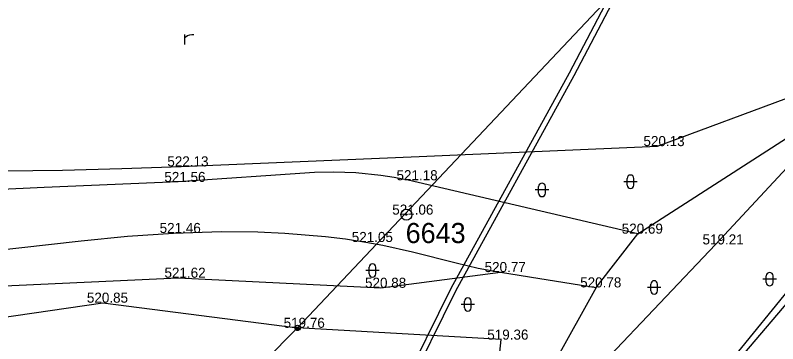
# Model space of a CAD drawing. Extents: x -669393 to -668650, y -1126925 to -1126294.
# Drawn here: x -668824.1 to -668767.3, y -1126837.8 to -1126813.3 of the extents above; entities that cross this region are included whole.
import ezdxf

# ---------------------------------------------------------------- set-up
doc = ezdxf.new("R2010")
doc.units = 0
for name, color, linetype in [('G_Bod_tecka', 7, 'Continuous'), ('G_Bod_vyska', 7, 'Continuous'), ('G_Bodove_pole', 7, 'Continuous'), ('G_Breh_Teren', 7, 'Continuous'), ('G_Plochy_zpevnene', 7, 'Continuous'), ('G_Site-Sloupy', 7, 'Continuous'), ('G_Z_ELsilove_nadz_kotovane', 7, 'Continuous'), ('G_Z_ELsilove_podz_kotovane', 7, 'Continuous'), ('G_Zelen-Znacky', 7, 'Continuous')]:
    doc.layers.add(name, color=color, linetype=linetype)

msp = doc.modelspace()

# ---------------------------------------------------------------- linework, layer by layer
at = {"layer": 'G_Bod_tecka'}
for p, q in [((-668776.23, -1126823.06), (-668776.23, -1126823.06)), ((-668811.72, -1126824.57), (-668811.72, -1126824.57)), ((-668811.94, -1126825.73), (-668811.94, -1126825.73)), ((-668794.8, -1126825.6), (-668794.8, -1126825.6)), ((-668794.93, -1126828.16), (-668794.93, -1126828.16)), ((-668812.28, -1126829.53), (-668812.28, -1126829.53)), ((-668777.69, -1126829.58), (-668777.69, -1126829.58)), ((-668797.96, -1126830.2), (-668797.96, -1126830.2)), ((-668771.91, -1126830.38), (-668771.91, -1126830.38)), ((-668787.92, -1126832.44), (-668787.92, -1126832.44)), ((-668811.93, -1126832.86), (-668811.93, -1126832.86)), ((-668796.83, -1126833.61), (-668796.83, -1126833.61)), ((-668780.8, -1126833.58), (-668780.8, -1126833.58)), ((-668817.55, -1126834.72), (-668817.55, -1126834.72)), ((-668803.04, -1126836.59), (-668803.04, -1126836.59)), ((-668787.87, -1126837.47), (-668787.87, -1126837.47))]:
    msp.add_line(p, q, dxfattribs=at)
at = {"layer": 'G_Bodove_pole'}
for radius in [0.412, 0.05]:
    msp.add_circle((-668794.93, -1126828.16), radius, dxfattribs=at)
at = {"layer": 'G_Breh_Teren'}
for p, q in [((-668757.59, -1126814.98), (-668771.91, -1126830.38)), ((-668772.4, -1126841.08), (-668751.76, -1126815.63)), ((-668776.23, -1126823.06), (-668765.35, -1126819.01)), ((-668777.69, -1126829.58), (-668765.86, -1126821.98)), ((-668771.91, -1126830.38), (-668789.08, -1126848.46)), ((-668796.83, -1126833.61), (-668787.92, -1126832.44)), ((-668827.59, -1126833.6), (-668811.93, -1126832.86)), ((-668811.93, -1126832.86), (-668796.83, -1126833.61)), ((-668780.8, -1126833.58), (-668789.08, -1126848.46)), ((-668830.9, -1126836.66), (-668817.55, -1126834.72)), ((-668817.55, -1126834.72), (-668803.04, -1126836.59)), ((-668787.87, -1126837.47), (-668803.04, -1126836.59)), ((-668789.08, -1126848.46), (-668787.87, -1126837.47))]:
    msp.add_line(p, q, dxfattribs=at)
msp.add_lwpolyline([(-668861.76, -1126825.07), (-668854.42, -1126825.02), (-668847.08, -1126824.98), (-668829.4, -1126824.94), (-668820.56, -1126824.84), (-668816.14, -1126824.73), (-668811.72, -1126824.57), (-668793.98, -1126823.82), (-668776.23, -1126823.06)], dxfattribs=at)
at = {"layer": 'G_Plochy_zpevnene'}
for p, q in [((-668785.44, -1126856.91), (-668751.27, -1126816.73)), ((-668777.69, -1126829.58), (-668794.8, -1126825.6)), ((-668780.8, -1126833.58), (-668777.69, -1126829.58))]:
    msp.add_line(p, q, dxfattribs=at)
for points in [[(-668794.8, -1126825.6), (-668795.84, -1126825.39), (-668796.83, -1126825.24), (-668798.69, -1126825.06), (-668800.34, -1126825.01), (-668801.78, -1126825.02), (-668811.94, -1126825.73), (-668821.93, -1126826.15), (-668831.92, -1126826.62), (-668839.86, -1126827.06), (-668847.81, -1126827.52), (-668851.35, -1126827.68), (-668854.02, -1126827.75), (-668858.01, -1126827.77), (-668862, -1126827.68), (-668863.7, -1126827.58), (-668865.18, -1126827.44), (-668867.77, -1126827.06), (-668869.7, -1126826.68), (-668871.12, -1126826.34), (-668873.25, -1126825.74), (-668875.33, -1126825.04), (-668886.78, -1126820.88), (-668897.18, -1126817.23)], [(-668826.04, -1126830.87), (-668819.16, -1126830.1), (-668815.72, -1126829.77), (-668812.28, -1126829.53), (-668808.7, -1126829.42), (-668806.01, -1126829.44), (-668803.99, -1126829.53), (-668800.97, -1126829.78), (-668799.46, -1126829.97), (-668797.96, -1126830.2), (-668796.69, -1126830.43), (-668794.49, -1126830.94), (-668791.22, -1126831.76), (-668789.58, -1126832.14), (-668787.92, -1126832.44), (-668784.36, -1126833.01), (-668780.8, -1126833.58)]]:
    msp.add_lwpolyline(points, dxfattribs=at)
at = {"layer": 'G_Site-Sloupy'}
msp.add_circle((-668803.04, -1126836.59), 0.2, dxfattribs=at)
for radius in [0.18, 0.16, 0.14, 0.12, 0.1, 0.08, 0.06, 0.04, 0.02]:
    msp.add_arc((-668803.04, -1126836.59), radius, 180, 0, dxfattribs=at)
at = {"layer": 'G_Z_ELsilove_nadz_kotovane'}
msp.add_lwpolyline([(-668760.642, -1126791.685), (-668778.872, -1126810.991), (-668779.891, -1126812.071), (-668803.039, -1126836.585), (-668840.228, -1126874.108)], dxfattribs=at)
at = {"layer": 'G_Z_ELsilove_podz_kotovane'}
for points in [[(-668689.689, -1126700.721), (-668717.926, -1126737.102), (-668731.142, -1126751.223), (-668740.945, -1126761.054), (-668764.235, -1126785.249), (-668764.468, -1126785.599), (-668771.608, -1126796.321), (-668779.891, -1126812.071), (-668782.816, -1126817.632), (-668791.63, -1126833.665), (-668795.332, -1126841.155), (-668801.598, -1126850.336), (-668806.75, -1126857.548), (-668807.082, -1126858.921), (-668805.909, -1126860.176), (-668789.068, -1126872.587), (-668784.608, -1126876.148)], [(-668689.548, -1126701.19), (-668717.622, -1126737.362), (-668730.854, -1126751.501), (-668740.659, -1126761.334), (-668763.921, -1126785.501), (-668764.234, -1126785.971), (-668771.264, -1126796.525), (-668778.872, -1126810.991), (-668782.464, -1126817.822), (-668791.276, -1126833.851), (-668794.986, -1126841.357), (-668801.27, -1126850.566), (-668806.38, -1126857.718), (-668806.642, -1126858.805), (-668805.641, -1126859.876), (-668788.824, -1126872.269), (-668784.068, -1126876.067)]]:
    msp.add_lwpolyline(points, dxfattribs=at)
at = {"layer": 'G_Zelen-Znacky'}
for p, q in [((-668811.44, -1126815.481), (-668811.44, -1126814.749)), ((-668777.74, -1126825.71), (-668778.74, -1126825.71)), ((-668778.49, -1126825.96), (-668778.49, -1126825.46)), ((-668777.99, -1126825.96), (-668777.99, -1126825.46)), ((-668784.33, -1126826.32), (-668785.33, -1126826.32)), ((-668785.08, -1126826.57), (-668785.08, -1126826.07)), ((-668784.58, -1126826.57), (-668784.58, -1126826.07)), ((-668797.71, -1126832.57), (-668797.71, -1126832.07)), ((-668797.21, -1126832.57), (-668797.21, -1126832.07)), ((-668796.96, -1126832.32), (-668797.96, -1126832.32)), ((-668768.12, -1126833.22), (-668768.12, -1126832.72)), ((-668767.62, -1126833.22), (-668767.62, -1126832.72)), ((-668767.37, -1126832.97), (-668768.37, -1126832.97)), ((-668775.98, -1126833.58), (-668776.98, -1126833.58)), ((-668776.73, -1126833.83), (-668776.73, -1126833.33)), ((-668776.23, -1126833.83), (-668776.23, -1126833.33)), ((-668789.86, -1126834.85), (-668790.86, -1126834.85)), ((-668790.61, -1126835.1), (-668790.61, -1126834.6)), ((-668790.11, -1126835.1), (-668790.11, -1126834.6))]:
    msp.add_line(p, q, dxfattribs=at)
msp.add_lwpolyline([(-668811.44, -1126814.985), (-668811.338, -1126814.89), (-668811.235, -1126814.827), (-668811.078, -1126814.78), (-668810.928, -1126814.757), (-668810.771, -1126814.749)], dxfattribs=at)
for centre, start, end in [((-668778.24, -1126825.46), 0, 180), ((-668784.83, -1126826.07), 0, 180), ((-668778.24, -1126825.96), 180, 0), ((-668784.83, -1126826.57), 180, 0), ((-668797.46, -1126832.07), 0, 180), ((-668797.46, -1126832.57), 180, 0), ((-668767.87, -1126832.72), 0, 180), ((-668776.48, -1126833.33), 0, 180), ((-668767.87, -1126833.22), 180, 0), ((-668776.48, -1126833.83), 180, 0), ((-668790.36, -1126834.6), 0, 180), ((-668790.36, -1126835.1), 180, 0)]:
    msp.add_arc(centre, 0.25, start, end, dxfattribs=at)

# ---------------------------------------------------------------- texts
at = {"layer": 'G_Bod_vyska'}
for s, p in [('520.13', (-668777.274, -1126823.06)), ('522.13', (-668812.742, -1126824.57)), ('521.56', (-668812.966, -1126825.73)), ('521.18', (-668795.671, -1126825.6)), ('521.06', (-668795.988, -1126828.16)), ('521.46', (-668813.316, -1126829.53)), ('520.69', (-668778.891, -1126829.58)), ('521.05', (-668799.004, -1126830.2)), ('519.21', (-668772.873, -1126830.38)), ('521.62', (-668812.956, -1126832.86)), ('520.77', (-668789.106, -1126832.44)), ('520.88', (-668798.016, -1126833.61)), ('520.78', (-668781.986, -1126833.58)), ('520.85', (-668818.736, -1126834.72)), ('519.76', (-668804.078, -1126836.59)), ('519.36', (-668788.908, -1126837.47))]:
    msp.add_text(s, height=0.75, dxfattribs=at).set_placement(p)
at = {"layer": 'G_Bodove_pole'}
msp.add_text('6643', height=1.5, dxfattribs=at).set_placement((-668794.985, -1126830.28))

doc.saveas('drawing.dxf')
